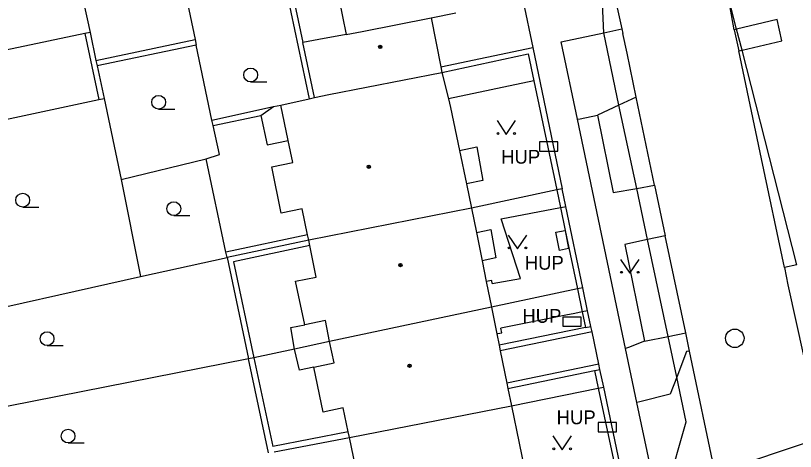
# Model space of a CAD drawing. Extents: x -596229 to -595156, y -1161237 to -1159376.
# Drawn here: x -595839.81 to -595797.54, y -1161054.1 to -1161030.47 of the extents above; entities that cross this region are included whole.
import ezdxf

# ---------------------------------------------------------------- set-up
doc = ezdxf.new("R2010")
doc.units = 0
for name, color, linetype in [('DOP - kresba z DSPS bez souradnic', 7, 'Continuous'), ('DOP - rozhrani ploch obecne', 7, 'Continuous'), ('Level 24', 7, 'Continuous'), ('Level 27', 7, 'Continuous'), ('Level 36', 7, 'Continuous'), ('Level 39', 7, 'Continuous'), ('plynovod - povrch.  znaky - PRIS skut. velikost', 7, 'Continuous'), ('Specificka linie pasportu komunikaci', 7, 'Continuous'), ('TM - budovy zdene_ betonove - VP', 7, 'Continuous'), ('TM - chodniky - VP', 7, 'Continuous'), ('TM - komunikace - VP', 7, 'Continuous'), ('TM - plot drateny_ kovovy - VP', 7, 'Continuous'), ('TM - podezdivka plotu - VP', 7, 'Continuous'), ('TM - popis objektu', 7, 'Continuous'), ('TM - rozhrani ploch obecne - VP', 7, 'Continuous'), ('TM - vjezd na pozemek', 7, 'Continuous')]:
    doc.layers.add(name, color=color, linetype=linetype)

msp = doc.modelspace()

# ---------------------------------------------------------------- linework, layer by layer
at = {"layer": 'DOP - kresba z DSPS bez souradnic'}
for points in [[(-595825.49, -1161027.45), (-595823.89, -1161034.98)], [(-595836.07, -1161031.45), (-595835.31, -1161035.02)], [(-595835.46, -1161032.9), (-595830.08, -1161031.77)], [(-595829.17, -1161036.14), (-595825.83, -1161035.4)], [(-595826.51, -1161035.89), (-595826.18, -1161037.48)], [(-595826.18, -1161037.48), (-595825.03, -1161037.24)], [(-595823.98, -1161042.36), (-595828.41, -1161043.3)], [(-595823.86, -1161042.94), (-595828, -1161043.82)], [(-595828, -1161043.82), (-595826.89, -1161049.02)], [(-595826.89, -1161049.02), (-595825.86, -1161053.83)], [(-595821.78, -1161053.04), (-595825.86, -1161053.83)]]:
    msp.add_lwpolyline(points, dxfattribs=at)
at = {"layer": 'DOP - rozhrani ploch obecne'}
for points in [[(-595830.75, -1161028.58), (-595830.08, -1161031.77)], [(-595825, -1161028.34), (-595824.24, -1161031.93)], [(-595835.78, -1161031.39), (-595835.46, -1161032.9)], [(-595830.08, -1161031.77), (-595830.02, -1161032.07)], [(-595830.02, -1161032.07), (-595835.4, -1161033.19)], [(-595829.17, -1161036.14), (-595830.02, -1161032.07)], [(-595835.46, -1161032.9), (-595835.4, -1161033.19)], [(-595835.4, -1161033.19), (-595835.02, -1161034.96)], [(-595835.31, -1161035.02), (-595835.02, -1161034.96)], [(-595835.02, -1161034.96), (-595834.09, -1161039.35)], [(-595845.86, -1161037.28), (-595835.31, -1161035.02)], [(-595826.51, -1161035.89), (-595825.83, -1161035.4)], [(-595825.83, -1161035.4), (-595825.44, -1161035.32)], [(-595829.1, -1161036.43), (-595829.17, -1161036.14)], [(-595829.1, -1161036.43), (-595826.51, -1161035.89)], [(-595828.76, -1161038.01), (-595829.1, -1161036.43)], [(-595834.09, -1161039.35), (-595829.49, -1161038.23)], [(-595829.49, -1161038.23), (-595828.76, -1161038.01)], [(-595828.41, -1161043.3), (-595829.49, -1161038.23)], [(-595834.09, -1161039.35), (-595833.04, -1161044.62)], [(-595823.92, -1161042.65), (-595828.35, -1161043.59)], [(-595828.35, -1161043.59), (-595828.41, -1161043.3)], [(-595833.04, -1161044.62), (-595828.35, -1161043.59)], [(-595828.35, -1161043.59), (-595827.18, -1161049.08)], [(-595843.85, -1161047.04), (-595833.04, -1161044.62)], [(-595822.79, -1161048.14), (-595824.7, -1161048.55)], [(-595824.7, -1161048.55), (-595826.89, -1161049.02)], [(-595827.18, -1161049.08), (-595847.92, -1161053.16)], [(-595826.89, -1161049.02), (-595827.18, -1161049.08)], [(-595826.1, -1161054.18), (-595827.18, -1161049.08)], [(-595825.8, -1161054.12), (-595821.72, -1161053.34)]]:
    msp.add_lwpolyline(points, dxfattribs=at)
at = {"layer": 'Level 24'}
for points in [[(-595811.418, -1161037.819), (-595810.418, -1161037.819), (-595810.418, -1161037.319), (-595811.418, -1161037.319)], [(-595810.148, -1161047.319), (-595809.148, -1161047.319), (-595809.148, -1161046.819), (-595810.148, -1161046.819)], [(-595808.228, -1161053.039), (-595807.228, -1161053.039), (-595807.228, -1161052.539), (-595808.228, -1161052.539)]]:
    msp.add_lwpolyline(points, close=True, dxfattribs=at)
at = {"layer": 'Level 27'}
msp.add_circle((-595800.82, -1161047.97), 0.5, dxfattribs=at)
at = {"layer": 'Level 36'}
for p, q in [((-595827.07, -1161034.065), (-595826.195, -1161034.065)), ((-595832.06, -1161035.545), (-595831.185, -1161035.545)), ((-595839.43, -1161040.855), (-595838.555, -1161040.855)), ((-595831.24, -1161041.315), (-595830.365, -1161041.315)), ((-595838.11, -1161048.365), (-595837.235, -1161048.365)), ((-595836.97, -1161053.645), (-595836.095, -1161053.645))]:
    msp.add_line(p, q, dxfattribs=at)
for points in [[(-595813.71, -1161036.16), (-595813.21, -1161036.91), (-595812.71, -1161036.16)], [(-595813.1, -1161042.37), (-595812.6, -1161043.12), (-595812.1, -1161042.37)], [(-595807.01, -1161043.69), (-595806.51, -1161044.44), (-595806.01, -1161043.69)], [(-595810.68, -1161053.26), (-595810.18, -1161054.01), (-595809.68, -1161053.26)]]:
    msp.add_lwpolyline(points, dxfattribs=at)
for centre, radius in [((-595827.07, -1161033.69), 0.375), ((-595832.06, -1161035.17), 0.375), ((-595813.66, -1161036.86), 0.05), ((-595812.761, -1161036.86), 0.05), ((-595839.43, -1161040.48), 0.375), ((-595831.24, -1161040.94), 0.375), ((-595813.05, -1161043.07), 0.05), ((-595812.151, -1161043.07), 0.05), ((-595806.96, -1161044.39), 0.05), ((-595806.061, -1161044.39), 0.05), ((-595838.11, -1161047.99), 0.375), ((-595836.97, -1161053.27), 0.375), ((-595810.63, -1161053.96), 0.05), ((-595809.731, -1161053.96), 0.05)]:
    msp.add_circle(centre, radius, dxfattribs=at)
at = {"layer": 'Level 39'}
for centre, radius in [((-595820.04, -1161032.17), 0.09), ((-595820.04, -1161032.17), 0.0398), ((-595820.67, -1161038.67), 0.09), ((-595820.67, -1161038.67), 0.0398), ((-595818.95, -1161044), 0.09), ((-595818.95, -1161044), 0.0398), ((-595818.45, -1161049.46), 0.09), ((-595818.45, -1161049.46), 0.0398)]:
    msp.add_circle(centre, radius, dxfattribs=at)
at = {"layer": 'plynovod - povrch.  znaky - PRIS skut. velikost'}
for points in [[(-595810.33, -1161043.2), (-595810.52, -1161042.22), (-595810.01, -1161042.12)], [(-595810.01, -1161042.12), (-595809.84, -1161043.1), (-595810.33, -1161043.2)]]:
    msp.add_lwpolyline(points, dxfattribs=at)
at = {"layer": 'Specificka linie pasportu komunikaci'}
for points in [[(-595807.35, -1161029.38), (-595806.95, -1161031.19)], [(-595800.86, -1161031.24), (-595801.18, -1161029.4)], [(-595800.43, -1161032.34), (-595798.27, -1161031.83), (-595798.53, -1161030.69), (-595800.72, -1161031.21)], [(-595807.93, -1161031.4), (-595806.95, -1161031.19)], [(-595806.95, -1161031.19), (-595806.89, -1161031.45)], [(-595806.16, -1161034.9), (-595806.66, -1161032.5), (-595806.89, -1161031.45)], [(-595800.72, -1161031.21), (-595800.86, -1161031.24)], [(-595800.86, -1161031.24), (-595800.6, -1161032.38)], [(-595800.6, -1161032.38), (-595800.43, -1161032.34)], [(-595798.13, -1161044.13), (-595799.37, -1161038.23), (-595800.6, -1161032.38)], [(-595811.71, -1161034), (-595816.35, -1161034.99)], [(-595806.16, -1161034.9), (-595807.1, -1161035.33)], [(-595805.17, -1161039.67), (-595806.16, -1161034.9)], [(-595807.1, -1161035.33), (-595808.26, -1161035.87)], [(-595809.35, -1161036.09), (-595809.21, -1161036.06), (-595808.26, -1161035.87)], [(-595808.26, -1161035.87), (-595807.42, -1161040.06), (-595806.14, -1161039.84)], [(-595815.75, -1161037.78), (-595814.81, -1161037.59), (-595814.48, -1161039.42), (-595815.37, -1161039.6)], [(-595806.14, -1161039.84), (-595805.17, -1161039.67)], [(-595805.17, -1161039.67), (-595804.6, -1161042.41)], [(-595813.97, -1161045), (-595812.44, -1161044.72), (-595813.48, -1161041.49), (-595810.27, -1161040.88)], [(-595810.27, -1161040.88), (-595810.05, -1161040.84), (-595809.98, -1161040.83)], [(-595814.83, -1161042.24), (-595814.05, -1161042.07), (-595813.78, -1161043.61), (-595814.52, -1161043.77)], [(-595805.55, -1161042.61), (-595806.79, -1161042.88), (-595805.72, -1161048.12)], [(-595804.6, -1161042.41), (-595805.55, -1161042.61)], [(-595803.48, -1161047.68), (-595804.6, -1161042.41)], [(-595797.46, -1161043.98), (-595798.13, -1161044.13)], [(-595798.13, -1161044.13), (-595797.95, -1161045.07), (-595797.08, -1161048.99), (-595796.9, -1161049.93)], [(-595813.97, -1161045), (-595814, -1161044.83), (-595814.3, -1161044.89)], [(-595809.09, -1161046.54), (-595809.49, -1161046.62), (-595809.98, -1161046.72), (-595813.51, -1161047.42)], [(-595808.8, -1161046.48), (-595809.09, -1161046.54)], [(-595813.73, -1161047.72), (-595813.67, -1161047.71), (-595813.46, -1161047.67), (-595813.51, -1161047.42)], [(-595808.91, -1161047.39), (-595808.62, -1161047.331)], [(-595804.44, -1161047.87), (-595803.48, -1161047.68)], [(-595803.28, -1161048.66), (-595803.48, -1161047.68)], [(-595805.72, -1161048.12), (-595806.58, -1161048.46), (-595806.74, -1161048.52)], [(-595805.72, -1161048.12), (-595804.44, -1161047.87)], [(-595803.28, -1161048.66), (-595803.44, -1161048.69), (-595803.97, -1161050.08)], [(-595801.89, -1161055.28), (-595803.28, -1161048.66)], [(-595808.42, -1161049.72), (-595808.129, -1161049.66)], [(-595803.97, -1161050.08), (-595804.32, -1161050.99), (-595805.97, -1161051.41), (-595806.13, -1161051.45)], [(-595801.89, -1161055.28), (-595796.13, -1161053.35)]]:
    msp.add_lwpolyline(points, dxfattribs=at)
at = {"layer": 'TM - budovy zdene_ betonove - VP'}
for points in [[(-595822.48, -1161028.54), (-595821.9, -1161031.49)], [(-595836.13, -1161029.74), (-595835.78, -1161031.39)], [(-595817.29, -1161030.59), (-595815.94, -1161030.32)], [(-595821.03, -1161031.33), (-595817.29, -1161030.59)], [(-595817.29, -1161030.59), (-595816.76, -1161033.24)], [(-595836.07, -1161031.45), (-595846.61, -1161033.66)], [(-595835.78, -1161031.39), (-595836.07, -1161031.45)], [(-595821.9, -1161031.49), (-595823.37, -1161031.77)], [(-595821.9, -1161031.49), (-595821.03, -1161031.33)], [(-595823.37, -1161031.77), (-595824.24, -1161031.93)], [(-595823.6, -1161034.92), (-595824.24, -1161031.93)], [(-595816.76, -1161033.24), (-595816.7, -1161033.55)], [(-595822.83, -1161034.74), (-595816.7, -1161033.55)], [(-595816.7, -1161033.55), (-595816.35, -1161034.99)], [(-595825.44, -1161035.32), (-595823.89, -1161034.98)], [(-595823.89, -1161034.98), (-595823.6, -1161034.92)], [(-595823.6, -1161034.92), (-595822.83, -1161034.74)], [(-595816.35, -1161034.99), (-595816.24, -1161035.46)], [(-595825.03, -1161037.24), (-595825.44, -1161035.32)], [(-595816.24, -1161035.46), (-595815.75, -1161037.78)], [(-595824.78, -1161038.44), (-595825.03, -1161037.24)], [(-595815.75, -1161037.78), (-595815.37, -1161039.6)], [(-595825.93, -1161038.68), (-595824.78, -1161038.44)], [(-595825.41, -1161041.18), (-595825.93, -1161038.68)], [(-595815.37, -1161039.6), (-595815.09, -1161040.92)], [(-595815.09, -1161040.92), (-595823.92, -1161042.65)], [(-595815.09, -1161040.92), (-595814.83, -1161042.24)], [(-595824.27, -1161040.94), (-595825.41, -1161041.18)], [(-595823.98, -1161042.36), (-595824.27, -1161040.94)], [(-595823.92, -1161042.65), (-595823.98, -1161042.36)], [(-595814.83, -1161042.24), (-595814.52, -1161043.77)], [(-595823.86, -1161042.94), (-595823.92, -1161042.65)], [(-595823.51, -1161044.65), (-595823.86, -1161042.94)], [(-595814.52, -1161043.77), (-595814.3, -1161044.89)], [(-595824.63, -1161044.88), (-595823.51, -1161044.65)], [(-595824.14, -1161047.23), (-595824.63, -1161044.88)], [(-595814.3, -1161044.89), (-595814.02, -1161046.28)], [(-595814.02, -1161046.28), (-595822.79, -1161048.14)], [(-595814.02, -1161046.28), (-595813.73, -1161047.72)], [(-595823.02, -1161047), (-595824.14, -1161047.23)], [(-595822.79, -1161048.14), (-595823.02, -1161047)], [(-595813.73, -1161047.72), (-595813.6, -1161048.35)], [(-595822.55, -1161049.3), (-595822.79, -1161048.14)], [(-595813.6, -1161048.35), (-595813.54, -1161048.65)], [(-595813.54, -1161048.65), (-595813.18, -1161050.4)], [(-595823.65, -1161049.54), (-595822.55, -1161049.3)], [(-595823.14, -1161051.98), (-595823.65, -1161049.54)], [(-595813.18, -1161050.4), (-595813.12, -1161050.69)], [(-595813.12, -1161050.69), (-595812.92, -1161051.64)], [(-595822.05, -1161051.74), (-595823.14, -1161051.98)], [(-595821.78, -1161053.04), (-595822.05, -1161051.74)], [(-595821.72, -1161053.34), (-595812.92, -1161051.64)], [(-595812.92, -1161051.64), (-595812.09, -1161055.68)], [(-595821.72, -1161053.34), (-595821.78, -1161053.04)], [(-595821.28, -1161055.45), (-595821.72, -1161053.34)]]:
    msp.add_lwpolyline(points, dxfattribs=at)
at = {"layer": 'TM - chodniky - VP'}
for points in [[(-595812.3, -1161029.71), (-595811.78, -1161032.2)], [(-595809.35, -1161036.09), (-595810.23, -1161031.89), (-595807.93, -1161031.4)], [(-595806.74, -1161048.52), (-595809.35, -1161036.09)], [(-595806.13, -1161051.45), (-595806.74, -1161048.52)], [(-595805.45, -1161054.68), (-595806.13, -1161051.45)]]:
    msp.add_lwpolyline(points, dxfattribs=at)
at = {"layer": 'TM - komunikace - VP'}
for points in [[(-595807.93, -1161031.4), (-595808.02, -1161029.42)], [(-595800.72, -1161031.21), (-595801.18, -1161029.4)], [(-595807.1, -1161035.33), (-595807.93, -1161031.4)], [(-595800.43, -1161032.34), (-595800.72, -1161031.21)], [(-595797.46, -1161043.98), (-595800.43, -1161032.34)], [(-595806.14, -1161039.84), (-595807.1, -1161035.33)], [(-595805.55, -1161042.61), (-595806.14, -1161039.84)], [(-595804.44, -1161047.87), (-595805.55, -1161042.61)], [(-595803.97, -1161050.08), (-595804.44, -1161047.87)], [(-595804.48, -1161056.11), (-595803.46, -1161052.5), (-595803.97, -1161050.08)]]:
    msp.add_lwpolyline(points, dxfattribs=at)
at = {"layer": 'TM - plot drateny_ kovovy - VP'}
for points in [[(-595816.7, -1161033.55), (-595812.02, -1161032.55)], [(-595812.02, -1161032.55), (-595811.71, -1161034)], [(-595811.71, -1161034), (-595810.47, -1161039.92)], [(-595810.47, -1161039.92), (-595810.27, -1161040.88)], [(-595810.27, -1161040.88), (-595810.01, -1161042.12)], [(-595810.01, -1161042.12), (-595809.35, -1161045.29)], [(-595809.35, -1161045.29), (-595809.09, -1161046.54)], [(-595809.09, -1161046.54), (-595808.91, -1161047.39)], [(-595808.91, -1161047.39), (-595813.6, -1161048.35)], [(-595813.12, -1161050.69), (-595808.42, -1161049.72)], [(-595808.42, -1161049.72), (-595808.22, -1161050.67)], [(-595808.22, -1161050.67), (-595807.35, -1161054.82)]]:
    msp.add_lwpolyline(points, dxfattribs=at)
at = {"layer": 'TM - podezdivka plotu - VP'}
for points in [[(-595816.76, -1161033.24), (-595811.78, -1161032.2)], [(-595811.78, -1161032.2), (-595810.18, -1161039.86)], [(-595809.98, -1161040.83), (-595810.18, -1161039.86)], [(-595809.06, -1161045.23), (-595809.98, -1161040.83)], [(-595808.8, -1161046.48), (-595809.06, -1161045.23)], [(-595808.62, -1161047.33), (-595808.8, -1161046.48)], [(-595808.56, -1161047.62), (-595813.54, -1161048.65)], [(-595808.56, -1161047.62), (-595808.62, -1161047.33)], [(-595808.19, -1161049.37), (-595813.18, -1161050.4)], [(-595808.13, -1161049.66), (-595808.19, -1161049.37)], [(-595807.93, -1161050.61), (-595808.13, -1161049.66)], [(-595807.06, -1161054.77), (-595807.93, -1161050.61)]]:
    msp.add_lwpolyline(points, dxfattribs=at)
at = {"layer": 'TM - rozhrani ploch obecne - VP'}
for points in [[(-595810.47, -1161039.92), (-595815.09, -1161040.92)], [(-595810.18, -1161039.86), (-595810.47, -1161039.92)], [(-595809.35, -1161045.29), (-595814.02, -1161046.28)], [(-595809.06, -1161045.23), (-595809.35, -1161045.29)], [(-595824.7, -1161048.55), (-595824.9, -1161047.39), (-595824.14, -1161047.23)], [(-595823.65, -1161049.54), (-595824.42, -1161049.7), (-595824.7, -1161048.55)], [(-595808.22, -1161050.67), (-595807.93, -1161050.61)], [(-595812.92, -1161051.64), (-595808.22, -1161050.67)]]:
    msp.add_lwpolyline(points, dxfattribs=at)
at = {"layer": 'TM - vjezd na pozemek'}
msp.add_lwpolyline([(-595808.19, -1161049.37), (-595808.56, -1161047.62)], dxfattribs=at)

# ---------------------------------------------------------------- texts
at = {"layer": 'TM - popis objektu'}
for p in [(-595813.49, -1161038.5), (-595812.21, -1161044.25), (-595812.34, -1161047.13), (-595810.48, -1161052.63)]:
    msp.add_text('HUP', height=0.75, dxfattribs=at).set_placement(p)

doc.saveas('drawing.dxf')
